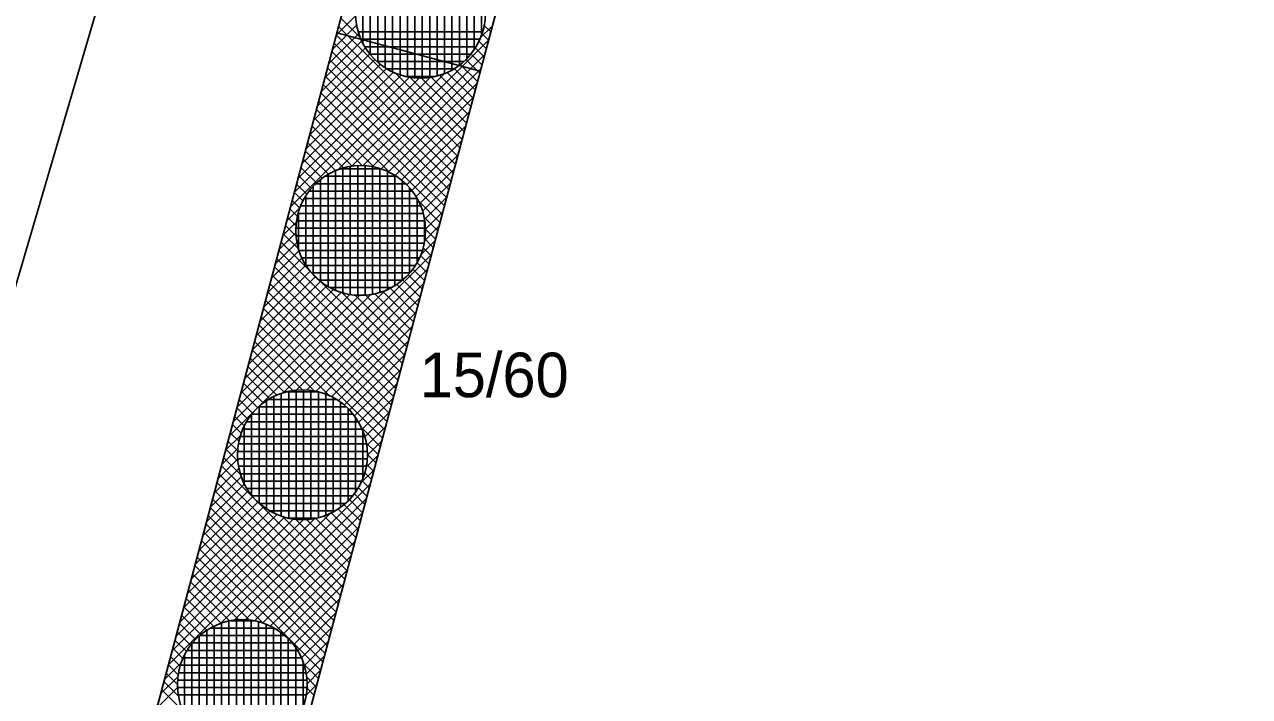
# Model space of a CAD drawing. Extents: x -566461 to -565198, y -1096301 to -1095707.
# Drawn here: x -565856.17 to -565823.16, y -1096102.78 to -1096084.68 of the extents above; entities that cross this region are included whole.
import ezdxf

# ---------------------------------------------------------------- set-up
doc = ezdxf.new("R2010")
doc.units = 0
for name, color, linetype in [('Vrstva 1', 7, 'Continuous'), ('Vrstva 40', 7, 'Continuous'), ('Vrstva 41', 7, 'Continuous'), ('Vrstva 42', 7, 'Continuous'), ('Vrstva 44', 7, 'Continuous')]:
    doc.layers.add(name, color=color, linetype=linetype)

msp = doc.modelspace()

# ---------------------------------------------------------------- linework, layer by layer
at = {"layer": 'Vrstva 1'}
for p, q in [((-565836.72, -1096024.67), (-565860.88, -1096106.94)), ((-565832.07, -1096026.09), (-565854, -1096108.33)), ((-565849.04, -1096105.26), (-565838.03, -1096063.98))]:
    msp.add_line(p, q, dxfattribs=at)
at = {"layer": 'Vrstva 41'}
for p, q in [((-565847.77, -1096084.966), (-565847.233, -1096084.43)), ((-565847.873, -1096085.352), (-565847.207, -1096084.686)), ((-565847.708, -1096084.736), (-565844.438, -1096088.006)), ((-565847.649, -1096084.513), (-565847.092, -1096085.069)), ((-565843.904, -1096085.06), (-565843.561, -1096084.717)), ((-565843.796, -1096084.688), (-565843.605, -1096084.88)), ((-565848.078, -1096086.123), (-565847.071, -1096085.116)), ((-565847.976, -1096085.738), (-565847.152, -1096084.914)), ((-565847.768, -1096084.959), (-565844.498, -1096088.23)), ((-565847.054, -1096088.493), (-565843.664, -1096085.103)), ((-565843.931, -1096085.119), (-565843.724, -1096085.327)), ((-565843.85, -1096084.918), (-565843.664, -1096085.103)), ((-565848.181, -1096086.509), (-565846.97, -1096085.298)), ((-565847.887, -1096085.406), (-565844.617, -1096088.676)), ((-565847.828, -1096085.183), (-565844.558, -1096088.453)), ((-565844.032, -1096085.302), (-565843.783, -1096085.55)), ((-565848.49, -1096087.666), (-565846.568, -1096085.745)), ((-565848.387, -1096087.28), (-565846.719, -1096085.612)), ((-565848.284, -1096086.895), (-565846.853, -1096085.463)), ((-565847.947, -1096085.629), (-565844.677, -1096088.899)), ((-565846.798, -1096088.52), (-565843.767, -1096085.489)), ((-565844.435, -1096085.747), (-565843.962, -1096086.22)), ((-565844.284, -1096085.615), (-565843.902, -1096085.997)), ((-565844.15, -1096085.466), (-565843.843, -1096085.773)), ((-565849.004, -1096089.595), (-565845.524, -1096086.115)), ((-565848.901, -1096089.209), (-565845.783, -1096086.09)), ((-565848.798, -1096088.823), (-565846.012, -1096086.037)), ((-565848.695, -1096088.437), (-565846.218, -1096085.96)), ((-565848.593, -1096088.052), (-565846.402, -1096085.861)), ((-565848.066, -1096086.076), (-565844.796, -1096089.346)), ((-565848.006, -1096085.853), (-565844.736, -1096089.123)), ((-565847.735, -1096088.608), (-565845.217, -1096086.09)), ((-565847.353, -1096088.509), (-565844.82, -1096085.976)), ((-565846.571, -1096088.575), (-565843.87, -1096085.875)), ((-565846.189, -1096085.972), (-565844.379, -1096087.783)), ((-565845.79, -1096086.089), (-565844.319, -1096087.56)), ((-565845.481, -1096086.115), (-565844.26, -1096087.336)), ((-565845.222, -1096086.091), (-565844.2, -1096087.113)), ((-565844.992, -1096086.038), (-565844.141, -1096086.89)), ((-565844.786, -1096085.962), (-565844.081, -1096086.666)), ((-565844.602, -1096085.863), (-565844.022, -1096086.443)), ((-565848.125, -1096086.299), (-565844.855, -1096089.569)), ((-565846.369, -1096088.657), (-565843.973, -1096086.26)), ((-565848.244, -1096086.746), (-565846.296, -1096088.694)), ((-565848.185, -1096086.523), (-565844.915, -1096089.793)), ((-565846.187, -1096088.757), (-565844.076, -1096086.646)), ((-565848.304, -1096086.969), (-565846.744, -1096088.529)), ((-565846.022, -1096088.875), (-565844.179, -1096087.032)), ((-565848.423, -1096087.416), (-565847.333, -1096088.506)), ((-565848.363, -1096087.192), (-565847.064, -1096088.492)), ((-565845.873, -1096089.009), (-565844.281, -1096087.417)), ((-565848.483, -1096087.639), (-565847.568, -1096088.554)), ((-565848.602, -1096088.086), (-565847.97, -1096088.718)), ((-565848.542, -1096087.862), (-565847.779, -1096088.625)), ((-565845.741, -1096089.159), (-565844.384, -1096087.803)), ((-565848.661, -1096088.309), (-565848.141, -1096088.829)), ((-565845.625, -1096089.326), (-565844.487, -1096088.189)), ((-565848.78, -1096088.755), (-565848.433, -1096089.102)), ((-565848.721, -1096088.532), (-565848.295, -1096088.957)), ((-565845.526, -1096089.511), (-565844.59, -1096088.575)), ((-565848.84, -1096088.979), (-565848.555, -1096089.264)), ((-565845.449, -1096089.716), (-565844.693, -1096088.96)), ((-565848.899, -1096089.202), (-565848.659, -1096089.442)), ((-565845.574, -1096089.416), (-565844.974, -1096090.016)), ((-565845.395, -1096089.946), (-565844.796, -1096089.346)), ((-565849.107, -1096089.98), (-565848.732, -1096089.605)), ((-565849.018, -1096089.649), (-565848.809, -1096089.858)), ((-565848.959, -1096089.425), (-565848.745, -1096089.639)), ((-565845.371, -1096090.204), (-565844.899, -1096089.732)), ((-565849.21, -1096090.366), (-565848.831, -1096089.987)), ((-565849.078, -1096089.872), (-565848.844, -1096090.106)), ((-565845.409, -1096089.864), (-565845.034, -1096090.239)), ((-565849.313, -1096090.752), (-565848.847, -1096090.286)), ((-565849.197, -1096090.319), (-565848.771, -1096090.744)), ((-565849.138, -1096090.095), (-565848.842, -1096090.391)), ((-565845.4, -1096090.516), (-565845.001, -1096090.117)), ((-565845.372, -1096090.184), (-565845.093, -1096090.462)), ((-565849.415, -1096091.137), (-565848.82, -1096090.542)), ((-565849.257, -1096090.542), (-565845.987, -1096093.812)), ((-565845.508, -1096090.907), (-565845.104, -1096090.503)), ((-565845.434, -1096090.688), (-565845.213, -1096090.909)), ((-565845.393, -1096090.446), (-565845.153, -1096090.686)), ((-565849.621, -1096091.909), (-565848.683, -1096090.971)), ((-565849.518, -1096091.523), (-565848.765, -1096090.769)), ((-565849.376, -1096090.988), (-565846.106, -1096094.258)), ((-565849.316, -1096090.765), (-565846.046, -1096094.035)), ((-565848.854, -1096094.536), (-565845.207, -1096090.889)), ((-565845.505, -1096090.899), (-565845.272, -1096091.132)), ((-565849.827, -1096092.68), (-565848.465, -1096091.318)), ((-565849.724, -1096092.294), (-565848.583, -1096091.153)), ((-565849.435, -1096091.212), (-565846.165, -1096094.482)), ((-565848.568, -1096094.533), (-565845.31, -1096091.275)), ((-565845.709, -1096091.261), (-565845.391, -1096091.579)), ((-565845.598, -1096091.09), (-565845.332, -1096091.356)), ((-565850.135, -1096093.837), (-565848.014, -1096091.715)), ((-565850.033, -1096093.451), (-565848.181, -1096091.599)), ((-565849.93, -1096093.066), (-565848.331, -1096091.467)), ((-565849.554, -1096091.658), (-565846.285, -1096094.928)), ((-565849.495, -1096091.435), (-565846.225, -1096094.705)), ((-565848.318, -1096094.565), (-565845.413, -1096091.66)), ((-565846.144, -1096091.675), (-565845.57, -1096092.249)), ((-565845.982, -1096091.553), (-565845.51, -1096092.025)), ((-565845.837, -1096091.415), (-565845.451, -1096091.802)), ((-565850.65, -1096095.766), (-565846.829, -1096091.945)), ((-565850.547, -1096095.38), (-565847.136, -1096091.969)), ((-565850.444, -1096094.994), (-565847.394, -1096091.945)), ((-565850.341, -1096094.609), (-565847.624, -1096091.891)), ((-565850.238, -1096094.223), (-565847.829, -1096091.814)), ((-565849.614, -1096091.882), (-565846.344, -1096095.152)), ((-565849.211, -1096094.61), (-565846.433, -1096091.832)), ((-565848.098, -1096094.628), (-565845.516, -1096092.046)), ((-565847.624, -1096091.891), (-565845.927, -1096093.588)), ((-565847.271, -1096091.962), (-565845.868, -1096093.365)), ((-565846.986, -1096091.964), (-565845.808, -1096093.142)), ((-565846.738, -1096091.929), (-565845.749, -1096092.919)), ((-565846.519, -1096091.865), (-565845.689, -1096092.695)), ((-565846.322, -1096091.779), (-565845.629, -1096092.472)), ((-565849.733, -1096092.328), (-565846.463, -1096095.598)), ((-565849.673, -1096092.105), (-565846.404, -1096095.375)), ((-565849.793, -1096092.552), (-565846.523, -1096095.821)), ((-565847.9, -1096094.713), (-565845.619, -1096092.432)), ((-565849.912, -1096092.998), (-565848.35, -1096094.56)), ((-565849.852, -1096092.775), (-565847.928, -1096094.699)), ((-565847.721, -1096094.817), (-565845.722, -1096092.817)), ((-565849.971, -1096093.221), (-565848.665, -1096094.528)), ((-565847.559, -1096094.937), (-565845.824, -1096093.203)), ((-565850.09, -1096093.668), (-565849.162, -1096094.597)), ((-565850.031, -1096093.445), (-565848.929, -1096094.547)), ((-565847.413, -1096095.074), (-565845.927, -1096093.589)), ((-565850.15, -1096093.891), (-565849.371, -1096094.67)), ((-565847.284, -1096095.228), (-565846.03, -1096093.975)), ((-565850.269, -1096094.338), (-565849.728, -1096094.879)), ((-565850.209, -1096094.115), (-565849.559, -1096094.765)), ((-565847.17, -1096095.398), (-565846.133, -1096094.36)), ((-565850.328, -1096094.561), (-565849.881, -1096095.008)), ((-565850.448, -1096095.008), (-565850.138, -1096095.318)), ((-565850.388, -1096094.785), (-565850.018, -1096095.155)), ((-565847.077, -1096095.587), (-565846.236, -1096094.746)), ((-565850.507, -1096095.231), (-565850.241, -1096095.498)), ((-565847.004, -1096095.797), (-565846.339, -1096095.132)), ((-565850.626, -1096095.678), (-565850.387, -1096095.917)), ((-565850.567, -1096095.454), (-565850.325, -1096095.696)), ((-565847.109, -1096095.518), (-565846.582, -1096096.045)), ((-565846.955, -1096096.031), (-565846.442, -1096095.517)), ((-565850.752, -1096096.151), (-565850.34, -1096095.739)), ((-565850.686, -1096095.901), (-565850.418, -1096096.169)), ((-565846.97, -1096095.94), (-565846.642, -1096096.268)), ((-565846.94, -1096096.299), (-565846.545, -1096095.903)), ((-565850.855, -1096096.537), (-565850.414, -1096096.096)), ((-565850.805, -1096096.348), (-565850.335, -1096096.818)), ((-565850.745, -1096096.124), (-565850.413, -1096096.456)), ((-565846.973, -1096096.615), (-565846.647, -1096096.289)), ((-565846.938, -1096096.255), (-565846.701, -1096096.491)), ((-565851.061, -1096097.308), (-565850.385, -1096096.632)), ((-565850.958, -1096096.923), (-565850.417, -1096096.382)), ((-565850.864, -1096096.571), (-565847.595, -1096099.841)), ((-565847.121, -1096097.045), (-565846.75, -1096096.675)), ((-565846.963, -1096096.513), (-565846.761, -1096096.715)), ((-565851.164, -1096097.694), (-565850.322, -1096096.852)), ((-565850.924, -1096096.794), (-565847.654, -1096100.064)), ((-565847.08, -1096096.961), (-565846.88, -1096097.161)), ((-565847.007, -1096096.752), (-565846.82, -1096096.938)), ((-565851.37, -1096098.465), (-565850.133, -1096097.229)), ((-565851.267, -1096098.08), (-565850.237, -1096097.05)), ((-565851.043, -1096097.241), (-565847.773, -1096100.511)), ((-565850.983, -1096097.018), (-565847.714, -1096100.287)), ((-565850.53, -1096100.738), (-565846.853, -1096097.06)), ((-565847.289, -1096097.318), (-565846.999, -1096097.608)), ((-565847.175, -1096097.149), (-565846.94, -1096097.384)), ((-565851.678, -1096099.622), (-565849.722, -1096097.666)), ((-565851.575, -1096099.237), (-565849.876, -1096097.537)), ((-565851.472, -1096098.851), (-565850.013, -1096097.391)), ((-565851.103, -1096097.464), (-565847.833, -1096100.734)), ((-565850.234, -1096100.724), (-565846.956, -1096097.446)), ((-565847.565, -1096097.608), (-565847.118, -1096098.054)), ((-565847.418, -1096097.471), (-565847.059, -1096097.831)), ((-565852.295, -1096101.937), (-565848.337, -1096097.978)), ((-565852.089, -1096101.165), (-565848.919, -1096097.995)), ((-565851.987, -1096100.78), (-565849.153, -1096097.946)), ((-565851.884, -1096100.394), (-565849.363, -1096097.873)), ((-565851.781, -1096100.008), (-565849.552, -1096097.78)), ((-565851.222, -1096097.911), (-565847.952, -1096101.18)), ((-565851.162, -1096097.687), (-565847.892, -1096100.957)), ((-565850.907, -1096100.831), (-565847.905, -1096097.829)), ((-565849.979, -1096100.752), (-565847.059, -1096097.832)), ((-565849.228, -1096097.925), (-565847.535, -1096099.617)), ((-565848.866, -1096098.003), (-565847.476, -1096099.394)), ((-565848.327, -1096097.977), (-565847.356, -1096098.947)), ((-565848.106, -1096097.915), (-565847.297, -1096098.724)), ((-565847.908, -1096097.831), (-565847.237, -1096098.501)), ((-565847.728, -1096097.728), (-565847.178, -1096098.278)), ((-565852.192, -1096101.551), (-565848.653, -1096098.012)), ((-565851.281, -1096098.134), (-565848.012, -1096101.404)), ((-565849.753, -1096100.809), (-565847.162, -1096098.217)), ((-565848.579, -1096098.008), (-565847.416, -1096099.171)), ((-565851.4, -1096098.581), (-565848.131, -1096101.85)), ((-565851.341, -1096098.357), (-565848.071, -1096101.627)), ((-565849.552, -1096100.891), (-565847.265, -1096098.603)), ((-565851.46, -1096098.804), (-565848.19, -1096102.074)), ((-565849.37, -1096100.992), (-565847.367, -1096098.989)), ((-565851.579, -1096099.251), (-565850.096, -1096100.733)), ((-565851.519, -1096099.027), (-565849.729, -1096100.818)), ((-565851.638, -1096099.474), (-565850.387, -1096100.725)), ((-565849.206, -1096101.11), (-565847.47, -1096099.375)), ((-565851.758, -1096099.92), (-565850.863, -1096100.815)), ((-565851.698, -1096099.697), (-565850.64, -1096100.755)), ((-565849.058, -1096101.245), (-565847.573, -1096099.76)), ((-565851.817, -1096100.144), (-565851.063, -1096100.898)), ((-565848.926, -1096101.396), (-565847.676, -1096100.146)), ((-565851.936, -1096100.59), (-565851.406, -1096101.12)), ((-565851.877, -1096100.367), (-565851.243, -1096101)), ((-565848.81, -1096101.563), (-565847.779, -1096100.532)), ((-565851.996, -1096100.814), (-565851.553, -1096101.256)), ((-565848.712, -1096101.748), (-565847.882, -1096100.917)), ((-565852.115, -1096101.26), (-565851.798, -1096101.577)), ((-565852.055, -1096101.037), (-565851.684, -1096101.408)), ((-565848.636, -1096101.955), (-565847.985, -1096101.303)), ((-565852.174, -1096101.483), (-565851.894, -1096101.763)), ((-565852.398, -1096102.322), (-565851.929, -1096101.853)), ((-565852.293, -1096101.93), (-565852.019, -1096102.205)), ((-565852.234, -1096101.707), (-565851.968, -1096101.972)), ((-565848.658, -1096101.889), (-565848.25, -1096102.297)), ((-565848.584, -1096102.186), (-565848.088, -1096101.689)), ((-565852.501, -1096102.708), (-565852.022, -1096102.23)), ((-565852.353, -1096102.153), (-565852.04, -1096102.467)), ((-565848.573, -1096102.256), (-565848.309, -1096102.52)), ((-565848.561, -1096102.445), (-565848.19, -1096102.075)), ((-565852.604, -1096103.094), (-565852.036, -1096102.526)), ((-565852.472, -1096102.6), (-565851.875, -1096103.197)), ((-565852.412, -1096102.377), (-565852.008, -1096102.781)), ((-565848.591, -1096102.758), (-565848.293, -1096102.46)), ((-565848.569, -1096102.543), (-565848.369, -1096102.743))]:
    msp.add_line(p, q, dxfattribs=at)
at = {"layer": 'Vrstva 42'}
msp.add_line((-565843.886, -1096085.936), (-565847.753, -1096084.904), dxfattribs=at)
msp.add_lwpolyline([(-565828.2, -1096027.12), (-565826.72, -1096023.51), (-565829.55, -1096025.32), (-565832.07, -1096026.09), (-565854, -1096108.33), (-565697.28, -1096140.23), (-565696.05, -1096136.4), (-565849.04, -1096105.26)], close=True, dxfattribs=at)
at = {"layer": 'Vrstva 44'}
for p, q in [((-565846.25, -1096085.959), (-565846.25, -1096082.8)), ((-565846.05, -1096086.039), (-565846.05, -1096082.721)), ((-565845.85, -1096086.093), (-565845.85, -1096082.667)), ((-565845.65, -1096086.122), (-565845.65, -1096082.637)), ((-565845.45, -1096086.127), (-565845.45, -1096082.632)), ((-565845.25, -1096086.111), (-565845.25, -1096082.65)), ((-565845.05, -1096086.071), (-565845.05, -1096082.691)), ((-565844.85, -1096086.003), (-565844.85, -1096082.756)), ((-565846.65, -1096085.696), (-565846.65, -1096083.063)), ((-565846.45, -1096085.85), (-565846.45, -1096082.912)), ((-565844.65, -1096085.908), (-565844.65, -1096082.852)), ((-565844.45, -1096085.78), (-565844.45, -1096082.982)), ((-565846.85, -1096085.491), (-565846.85, -1096083.269)), ((-565844.25, -1096085.602), (-565844.25, -1096083.157)), ((-565844.05, -1096085.356), (-565844.05, -1096083.401)), ((-565847.05, -1096085.188), (-565847.05, -1096083.572)), ((-565843.85, -1096084.959), (-565843.85, -1096083.801)), ((-565843.825, -1096084.88), (-565847.175, -1096084.88)), ((-565843.898, -1096085.08), (-565847.103, -1096085.08)), ((-565844, -1096085.28), (-565846.999, -1096085.28)), ((-565844.141, -1096085.48), (-565846.859, -1096085.48)), ((-565844.329, -1096085.68), (-565846.669, -1096085.68)), ((-565844.599, -1096085.88), (-565846.398, -1096085.88)), ((-565845.091, -1096086.08), (-565845.912, -1096086.08)), ((-565847.99, -1096091.74), (-565847.99, -1096088.719)), ((-565847.79, -1096091.841), (-565847.79, -1096088.619)), ((-565846.56, -1096088.57), (-565847.658, -1096088.57)), ((-565847.59, -1096091.912), (-565847.59, -1096088.548)), ((-565847.39, -1096091.956), (-565847.39, -1096088.504)), ((-565847.19, -1096091.977), (-565847.19, -1096088.484)), ((-565846.99, -1096091.976), (-565846.99, -1096088.486)), ((-565846.79, -1096091.949), (-565846.79, -1096088.511)), ((-565846.59, -1096091.899), (-565846.59, -1096088.559)), ((-565846.39, -1096091.823), (-565846.39, -1096088.637)), ((-565846.19, -1096091.718), (-565846.19, -1096088.743)), ((-565848.39, -1096091.421), (-565848.39, -1096089.039)), ((-565845.897, -1096088.97), (-565848.323, -1096088.97)), ((-565848.19, -1096091.607), (-565848.19, -1096088.854)), ((-565846.146, -1096088.77), (-565848.072, -1096088.77)), ((-565845.99, -1096091.572), (-565845.99, -1096088.886)), ((-565845.79, -1096091.377), (-565845.79, -1096089.083)), ((-565845.587, -1096089.37), (-565848.633, -1096089.37)), ((-565848.59, -1096091.16), (-565848.59, -1096089.299)), ((-565845.72, -1096089.17), (-565848.501, -1096089.17)), ((-565845.59, -1096091.094), (-565845.59, -1096089.365)), ((-565848.79, -1096090.713), (-565848.79, -1096089.747)), ((-565845.491, -1096089.57), (-565848.729, -1096089.57)), ((-565845.381, -1096089.97), (-565848.84, -1096089.97)), ((-565845.424, -1096089.77), (-565848.797, -1096089.77)), ((-565845.39, -1096090.546), (-565845.39, -1096089.918)), ((-565845.362, -1096090.17), (-565848.858, -1096090.17)), ((-565845.366, -1096090.37), (-565848.852, -1096090.37)), ((-565845.395, -1096090.57), (-565848.825, -1096090.57)), ((-565845.447, -1096090.77), (-565848.774, -1096090.77)), ((-565845.525, -1096090.97), (-565848.695, -1096090.97)), ((-565845.635, -1096091.17), (-565848.584, -1096091.17)), ((-565845.784, -1096091.37), (-565848.438, -1096091.37)), ((-565845.987, -1096091.57), (-565848.233, -1096091.57)), ((-565846.283, -1096091.77), (-565847.939, -1096091.77)), ((-565846.94, -1096091.97), (-565847.282, -1096091.97)), ((-565849.45, -1096097.84), (-565849.45, -1096094.699)), ((-565849.25, -1096097.922), (-565849.25, -1096094.617)), ((-565848.233, -1096094.58), (-565849.131, -1096094.58)), ((-565849.05, -1096097.98), (-565849.05, -1096094.561)), ((-565848.85, -1096098.01), (-565848.85, -1096094.529)), ((-565848.65, -1096098.018), (-565848.65, -1096094.521)), ((-565848.45, -1096098.003), (-565848.45, -1096094.537)), ((-565848.25, -1096097.966), (-565848.25, -1096094.576)), ((-565848.05, -1096097.902), (-565848.05, -1096094.639)), ((-565847.5, -1096094.98), (-565849.861, -1096094.98)), ((-565849.85, -1096097.569), (-565849.85, -1096094.97)), ((-565849.65, -1096097.725), (-565849.65, -1096094.815)), ((-565847.766, -1096094.78), (-565849.597, -1096094.78)), ((-565847.85, -1096097.808), (-565847.85, -1096094.73)), ((-565847.65, -1096097.684), (-565847.65, -1096094.858)), ((-565847.45, -1096097.512), (-565847.45, -1096095.025)), ((-565850.05, -1096097.356), (-565850.05, -1096095.184)), ((-565847.313, -1096095.18), (-565850.047, -1096095.18)), ((-565847.25, -1096097.276), (-565847.25, -1096095.263)), ((-565847.072, -1096095.58), (-565850.286, -1096095.58)), ((-565850.25, -1096097.039), (-565850.25, -1096095.5)), ((-565847.175, -1096095.38), (-565850.187, -1096095.38)), ((-565847.05, -1096096.904), (-565847.05, -1096095.638)), ((-565846.956, -1096095.98), (-565850.405, -1096095.98)), ((-565847.002, -1096095.78), (-565850.358, -1096095.78)), ((-565846.934, -1096096.18), (-565850.427, -1096096.18)), ((-565846.934, -1096096.38), (-565850.425, -1096096.38)), ((-565846.959, -1096096.58), (-565850.4, -1096096.58)), ((-565847.008, -1096096.78), (-565850.352, -1096096.78)), ((-565847.082, -1096096.98), (-565850.279, -1096096.98)), ((-565847.185, -1096097.18), (-565850.173, -1096097.18)), ((-565847.33, -1096097.38), (-565850.031, -1096097.38)), ((-565847.521, -1096097.58), (-565849.837, -1096097.58)), ((-565847.798, -1096097.78), (-565849.561, -1096097.78)), ((-565848.317, -1096097.98), (-565849.05, -1096097.98)), ((-565849.436, -1096100.94), (-565851.163, -1096100.94)), ((-565851.06, -1096104.035), (-565851.06, -1096100.885)), ((-565850.86, -1096104.116), (-565850.86, -1096100.804)), ((-565850.66, -1096104.172), (-565850.66, -1096100.749)), ((-565849.986, -1096100.74), (-565850.62, -1096100.74)), ((-565850.46, -1096104.201), (-565850.46, -1096100.718)), ((-565850.26, -1096104.208), (-565850.26, -1096100.711)), ((-565850.06, -1096104.192), (-565850.06, -1096100.728)), ((-565849.86, -1096104.153), (-565849.86, -1096100.768)), ((-565849.66, -1096104.087), (-565849.66, -1096100.833)), ((-565849.46, -1096103.993), (-565849.46, -1096100.926)), ((-565851.46, -1096103.768), (-565851.46, -1096101.152)), ((-565849.154, -1096101.14), (-565851.446, -1096101.14)), ((-565851.26, -1096103.923), (-565851.26, -1096100.998)), ((-565849.26, -1096103.867), (-565849.26, -1096101.055)), ((-565849.06, -1096103.692), (-565849.06, -1096101.226)), ((-565848.814, -1096101.54), (-565851.787, -1096101.54)), ((-565851.66, -1096103.559), (-565851.66, -1096101.362)), ((-565848.956, -1096101.34), (-565851.642, -1096101.34)), ((-565848.86, -1096103.451), (-565848.86, -1096101.466)), ((-565848.63, -1096101.94), (-565851.969, -1096101.94)), ((-565848.706, -1096101.74), (-565851.894, -1096101.74)), ((-565851.86, -1096103.249), (-565851.86, -1096101.671)), ((-565848.66, -1096103.071), (-565848.66, -1096101.855)), ((-565848.581, -1096102.14), (-565852.019, -1096102.14)), ((-565848.553, -1096102.54), (-565852.048, -1096102.54)), ((-565848.556, -1096102.34), (-565852.045, -1096102.34)), ((-565848.573, -1096102.74), (-565852.026, -1096102.74))]:
    msp.add_line(p, q, dxfattribs=at)
for centre in [(-565845.5, -1096084.38), (-565847.11, -1096090.23), (-565848.68, -1096096.27), (-565850.3, -1096102.46)]:
    msp.add_circle(centre, 1.75, dxfattribs=at)

# ---------------------------------------------------------------- texts
at = {"layer": 'Vrstva 40'}
msp.add_text('15/60', height=1.2, dxfattribs=at).set_placement((-565845.52, -1096094.72))

doc.saveas('drawing.dxf')
